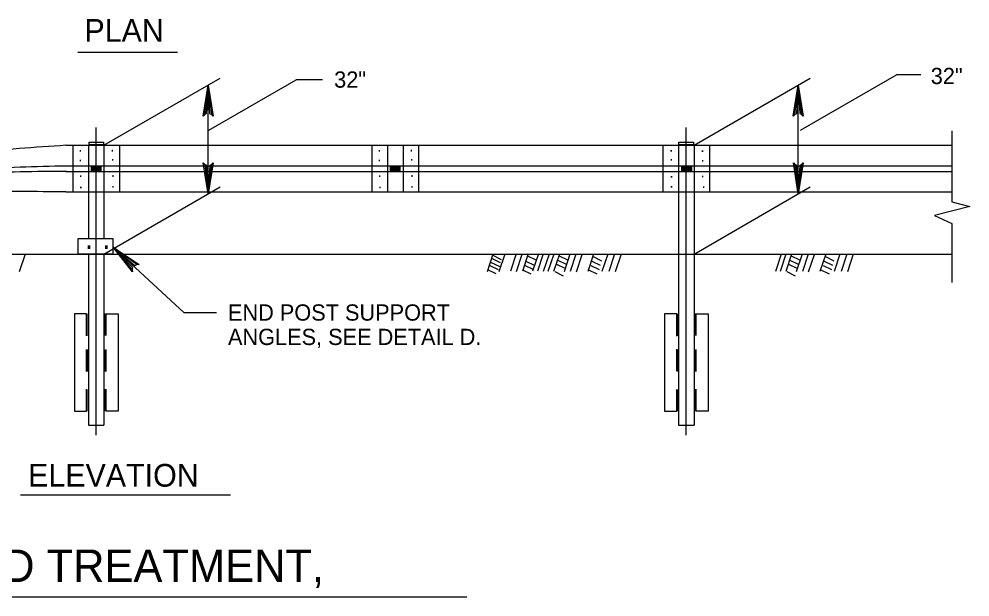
# Model space of a CAD drawing. Extents: x 637628 to 640188, y 298266 to 300751.
# Drawn here: x 638462.3 to 638638, y 298435.6 to 298542.3 of the extents above; entities that cross this region are included whole.
import ezdxf

# ---------------------------------------------------------------- set-up
doc = ezdxf.new("R2010")
doc.units = 0
doc.layers.add('2', color=7, linetype='Continuous')
doc.layers.add('3', color=7, linetype='Continuous')

msp = doc.modelspace()

# ---------------------------------------------------------------- linework, layer by layer
at = {"layer": '2'}
for p, q in [((638478.02, 298518.96), (638499.51, 298531.36)), ((638497.4, 298521.73), (638513.51, 298531.03)), ((638518.4, 298531.03), (638513.51, 298531.03)), ((638587.04, 298518.96), (638608.52, 298531.36)), ((638606.72, 298521.73), (638624.43, 298531.95)), ((638628.94, 298531.95), (638624.43, 298531.95)), ((638497.28, 298509.99), (638497.28, 298530.08)), ((638606.29, 298509.99), (638606.29, 298530.08)), ((638476.59, 298465.42), (638476.59, 298522.27)), ((638585.6, 298465.42), (638585.6, 298522.27)), ((638634.69, 298521.61), (638634.69, 298508.53)), ((638471, 298518.96), (638634.69, 298518.96)), ((638472.29, 298518.96), (638472.29, 298510.34)), ((638475.15, 298518.96), (638475.15, 298510.35)), ((638478.02, 298518.96), (638478.02, 298510.35)), ((638480.89, 298518.96), (638480.89, 298510.34)), ((638527.53, 298518.96), (638527.53, 298510.34)), ((638530.4, 298518.96), (638530.4, 298510.35)), ((638533.27, 298518.96), (638533.27, 298510.35)), ((638536.13, 298518.96), (638536.13, 298510.34)), ((638581.3, 298518.96), (638581.3, 298510.34)), ((638584.17, 298518.96), (638584.17, 298510.35)), ((638587.04, 298518.96), (638587.04, 298510.35)), ((638589.9, 298518.96), (638589.9, 298510.34)), ((638471, 298515.17), (638634.69, 298515.17)), ((638471, 298514.14), (638634.69, 298514.14)), ((638478.02, 298498.88), (638499.51, 298511.28)), ((638587.04, 298498.88), (638608.52, 298511.28)), ((638471, 298510.35), (638634.69, 298510.35)), ((638475.15, 298510.35), (638475.15, 298501.77)), ((638478.02, 298510.35), (638478.02, 298501.77)), ((638584.17, 298510.35), (638584.17, 298498.88)), ((638587.04, 298510.35), (638587.04, 298498.88)), ((638634.69, 298504.49), (638634.69, 298493.65)), ((638338.78, 298498.88), (638634.69, 298498.88)), ((638463.46, 298498.83), (638462.38, 298495.61)), ((638475.15, 298498.88), (638475.15, 298467.32)), ((638478.02, 298498.88), (638478.02, 298467.32)), ((638549.89, 298498.83), (638548.82, 298495.61)), ((638552.07, 298498.83), (638551, 298495.61)), ((638554.18, 298498.94), (638553.11, 298495.73)), ((638555.22, 298498.81), (638554.15, 298495.59)), ((638556.41, 298498.94), (638555.33, 298495.73)), ((638558.27, 298498.94), (638557.2, 298495.73)), ((638559.18, 298498.94), (638558.1, 298495.73)), ((638560.25, 298498.88), (638559.18, 298495.66)), ((638561.11, 298498.88), (638560.03, 298495.66)), ((638562.16, 298498.88), (638561.09, 298495.66)), ((638564.09, 298498.83), (638563.02, 298495.61)), ((638565.22, 298498.87), (638564.15, 298495.66)), ((638566.32, 298498.76), (638565.24, 298495.55)), ((638568.48, 298498.88), (638567.41, 298495.66)), ((638571.08, 298498.88), (638570.01, 298495.66)), ((638572.37, 298498.88), (638571.3, 298495.66)), ((638573.56, 298498.83), (638572.48, 298495.61)), ((638584.17, 298498.88), (638584.17, 298467.32)), ((638587.04, 298498.88), (638587.04, 298467.32)), ((638603.14, 298498.88), (638602.07, 298495.66)), ((638604, 298498.88), (638602.93, 298495.66)), ((638605.06, 298498.88), (638603.99, 298495.66)), ((638606.99, 298498.83), (638605.92, 298495.61)), ((638608.12, 298498.87), (638607.05, 298495.66)), ((638609.21, 298498.76), (638608.14, 298495.55)), ((638611.37, 298498.88), (638610.3, 298495.66)), ((638613.98, 298498.88), (638612.91, 298495.66)), ((638615.27, 298498.88), (638614.19, 298495.66)), ((638616.45, 298498.83), (638615.38, 298495.61)), ((638549.46, 298497.41), (638551.27, 298496.51)), ((638549.71, 298498.08), (638551.22, 298497.33)), ((638549.89, 298498.65), (638551.4, 298497.89)), ((638555.96, 298497.59), (638557.5, 298496.82)), ((638556.27, 298498.58), (638557.82, 298497.81)), ((638561.6, 298497.03), (638563.14, 298496.26)), ((638561.85, 298497.77), (638563.39, 298497)), ((638562.1, 298498.58), (638563.64, 298497.81)), ((638568.16, 298497.59), (638569.71, 298496.82)), ((638568.41, 298498.4), (638569.95, 298497.63)), ((638604.5, 298497.03), (638606.04, 298496.26)), ((638604.74, 298497.77), (638606.29, 298497)), ((638604.99, 298498.58), (638606.54, 298497.81)), ((638611.06, 298497.59), (638612.6, 298496.82)), ((638611.31, 298498.4), (638612.85, 298497.63)), ((638549.02, 298495.97), (638550.44, 298495.26)), ((638549.33, 298496.78), (638550.87, 298496.01)), ((638555.33, 298495.97), (638556.88, 298495.2)), ((638555.71, 298496.85), (638557.26, 298496.08)), ((638561.29, 298495.66), (638562.83, 298494.89)), ((638567.54, 298495.97), (638569.08, 298495.2)), ((638567.98, 298496.78), (638569.53, 298496.01)), ((638604.18, 298495.66), (638605.73, 298494.89)), ((638610.43, 298495.97), (638611.98, 298495.2)), ((638610.88, 298496.78), (638612.42, 298496.01)), ((638475.01, 298487.83), (638475.01, 298483.79)), ((638478.21, 298487.88), (638478.21, 298483.85)), ((638584.02, 298487.83), (638584.02, 298483.79)), ((638587.22, 298487.88), (638587.22, 298483.85)), ((638474.98, 298481.25), (638474.98, 298477.22)), ((638478.15, 298481.22), (638478.15, 298477.19)), ((638583.99, 298481.25), (638583.99, 298477.22)), ((638587.16, 298481.22), (638587.16, 298477.19)), ((638475.01, 298473.9), (638475.01, 298469.87)), ((638478.24, 298473.93), (638478.24, 298469.89)), ((638584.02, 298473.9), (638584.02, 298469.87)), ((638587.25, 298473.93), (638587.25, 298469.89)), ((638475.15, 298467.32), (638478.02, 298467.32)), ((638584.17, 298467.32), (638587.04, 298467.32))]:
    msp.add_line(p, q, dxfattribs=at)
for points in [[(638496.6, 298524.63), (638496.99, 298524.83), (638497.28, 298530.08), (638496.6, 298524.63), (638496.36, 298524.35), (638497.28, 298530.08), (638497.54, 298524.84), (638497.93, 298524.64), (638497.28, 298530.08), (638498.19, 298524.35), (638497.93, 298524.64)], [(638605.61, 298524.63), (638606, 298524.83), (638606.29, 298530.08), (638605.61, 298524.63), (638605.37, 298524.35), (638606.29, 298530.08), (638606.55, 298524.84), (638606.94, 298524.64), (638606.29, 298530.08), (638607.2, 298524.35), (638606.94, 298524.64)], [(638497.96, 298515.44), (638497.57, 298515.24), (638497.28, 298509.99), (638497.96, 298515.44), (638498.2, 298515.72), (638497.28, 298509.99), (638497.02, 298515.24), (638496.63, 298515.43), (638497.28, 298509.99), (638496.37, 298515.72), (638496.63, 298515.43)], [(638606.98, 298515.44), (638606.58, 298515.24), (638606.29, 298509.99), (638606.98, 298515.44), (638607.22, 298515.72), (638606.29, 298509.99), (638606.03, 298515.24), (638605.64, 298515.43), (638606.29, 298509.99), (638605.38, 298515.72), (638605.64, 298515.43)], [(638634.69, 298508.53), (638638.01, 298507.67), (638631.48, 298505.98), (638634.69, 298504.49)], [(638498.84, 298488.02), (638492.84, 298488.02), (638479.69, 298500.14)], [(638483.23, 298495.95), (638483.35, 298496.37), (638479.69, 298500.14), (638483.23, 298495.95), (638483.27, 298495.58), (638479.69, 298500.14), (638483.72, 298496.78), (638484.12, 298496.94), (638479.69, 298500.14), (638484.51, 298496.93), (638484.12, 298496.94)], [(638474.81, 298483.77), (638474.81, 298487.85), (638472.58, 298487.85), (638472.58, 298469.85), (638474.81, 298469.85), (638474.81, 298473.94)], [(638478.4, 298483.84), (638478.4, 298487.86), (638480.63, 298487.86), (638480.63, 298469.86), (638478.4, 298469.86), (638478.4, 298473.91)], [(638583.83, 298483.7), (638583.83, 298487.85), (638581.59, 298487.85), (638581.59, 298469.85), (638583.83, 298469.85), (638583.83, 298473.9)], [(638587.41, 298483.86), (638587.41, 298487.86), (638589.65, 298487.86), (638589.65, 298469.86), (638587.41, 298469.86), (638587.41, 298473.93)], [(638474.81, 298477.23), (638474.81, 298481.24)], [(638478.4, 298477.2), (638478.4, 298481.24)], [(638583.83, 298477.25), (638583.83, 298481.32)], [(638587.41, 298477.19), (638587.41, 298481.25)]]:
    msp.add_lwpolyline(points, dxfattribs=at)
for points in [[(638475.26, 298519.07), (638475.26, 298519.53), (638477.96, 298519.53), (638477.96, 298519.07)], [(638584.23, 298519.04), (638584.23, 298519.51), (638586.93, 298519.51), (638586.93, 298519.04)], [(638475.7, 298514.18), (638475.7, 298515.11), (638477.47, 298515.11), (638477.47, 298514.18)], [(638475.73, 298514.2), (638475.73, 298515.09), (638477.41, 298515.09), (638477.41, 298514.2)], [(638475.77, 298514.23), (638475.77, 298515.07), (638477.36, 298515.07), (638477.36, 298514.23)], [(638475.8, 298514.25), (638475.8, 298515.05), (638477.31, 298515.05), (638477.31, 298514.25)], [(638475.83, 298514.27), (638475.83, 298515.03), (638477.26, 298515.03), (638477.26, 298514.27)], [(638475.85, 298514.29), (638475.85, 298515.02), (638477.22, 298515.02), (638477.22, 298514.29)], [(638475.88, 298514.31), (638475.88, 298515), (638477.18, 298515), (638477.18, 298514.31)], [(638475.9, 298514.33), (638475.9, 298514.98), (638477.14, 298514.98), (638477.14, 298514.33)], [(638475.93, 298514.35), (638475.93, 298514.97), (638477.1, 298514.97), (638477.1, 298514.35)], [(638475.95, 298514.36), (638475.95, 298514.95), (638477.07, 298514.95), (638477.07, 298514.36)], [(638475.98, 298514.38), (638475.98, 298514.94), (638477.04, 298514.94), (638477.04, 298514.38)], [(638476.01, 298514.39), (638476.01, 298514.92), (638477.02, 298514.92), (638477.02, 298514.39)], [(638476.04, 298514.4), (638476.04, 298514.91), (638476.99, 298514.91), (638476.99, 298514.4)], [(638476.07, 298514.41), (638476.07, 298514.89), (638476.98, 298514.89), (638476.98, 298514.41)], [(638476.09, 298514.42), (638476.09, 298514.88), (638476.95, 298514.88), (638476.95, 298514.42)], [(638476.11, 298514.43), (638476.11, 298514.87), (638476.93, 298514.87), (638476.93, 298514.43)], [(638476.14, 298514.44), (638476.14, 298514.86), (638476.92, 298514.86), (638476.92, 298514.44)], [(638476.16, 298514.45), (638476.16, 298514.84), (638476.9, 298514.84), (638476.9, 298514.45)], [(638476.18, 298514.46), (638476.18, 298514.83), (638476.88, 298514.83), (638476.88, 298514.46)], [(638476.2, 298514.47), (638476.2, 298514.82), (638476.87, 298514.82), (638476.87, 298514.47)], [(638476.22, 298514.48), (638476.22, 298514.81), (638476.85, 298514.81), (638476.85, 298514.48)], [(638476.23, 298514.49), (638476.23, 298514.8), (638476.84, 298514.8), (638476.84, 298514.49)], [(638476.25, 298514.49), (638476.25, 298514.8), (638476.82, 298514.8), (638476.82, 298514.49)], [(638476.26, 298514.5), (638476.26, 298514.79), (638476.81, 298514.79), (638476.81, 298514.5)], [(638476.28, 298514.51), (638476.28, 298514.78), (638476.8, 298514.78), (638476.8, 298514.51)], [(638476.29, 298514.51), (638476.29, 298514.77), (638476.79, 298514.77), (638476.79, 298514.51)], [(638476.31, 298514.52), (638476.31, 298514.77), (638476.77, 298514.77), (638476.77, 298514.52)], [(638476.32, 298514.52), (638476.32, 298514.76), (638476.76, 298514.76), (638476.76, 298514.52)], [(638476.33, 298514.53), (638476.33, 298514.75), (638476.75, 298514.75), (638476.75, 298514.53)], [(638476.34, 298514.53), (638476.34, 298514.75), (638476.74, 298514.75), (638476.74, 298514.53)], [(638476.35, 298514.54), (638476.35, 298514.74), (638476.73, 298514.74), (638476.73, 298514.54)], [(638476.36, 298514.54), (638476.36, 298514.73), (638476.73, 298514.73), (638476.73, 298514.54)], [(638476.37, 298514.55), (638476.37, 298514.73), (638476.72, 298514.73), (638476.72, 298514.55)], [(638476.38, 298514.55), (638476.38, 298514.72), (638476.71, 298514.72), (638476.71, 298514.55)], [(638476.39, 298514.56), (638476.39, 298514.72), (638476.7, 298514.72), (638476.7, 298514.56)], [(638530.94, 298514.18), (638530.94, 298515.11), (638532.71, 298515.11), (638532.71, 298514.18)], [(638530.97, 298514.2), (638530.97, 298515.09), (638532.65, 298515.09), (638532.65, 298514.2)], [(638531.01, 298514.23), (638531.01, 298515.07), (638532.6, 298515.07), (638532.6, 298514.23)], [(638531.04, 298514.25), (638531.04, 298515.05), (638532.55, 298515.05), (638532.55, 298514.25)], [(638531.07, 298514.27), (638531.07, 298515.03), (638532.5, 298515.03), (638532.5, 298514.27)], [(638531.09, 298514.29), (638531.09, 298515.02), (638532.46, 298515.02), (638532.46, 298514.29)], [(638531.12, 298514.31), (638531.12, 298515), (638532.42, 298515), (638532.42, 298514.31)], [(638531.14, 298514.33), (638531.14, 298514.98), (638532.38, 298514.98), (638532.38, 298514.33)], [(638531.17, 298514.35), (638531.17, 298514.97), (638532.34, 298514.97), (638532.34, 298514.35)], [(638531.19, 298514.36), (638531.19, 298514.95), (638532.31, 298514.95), (638532.31, 298514.36)], [(638531.22, 298514.38), (638531.22, 298514.94), (638532.28, 298514.94), (638532.28, 298514.38)], [(638531.25, 298514.39), (638531.25, 298514.92), (638532.26, 298514.92), (638532.26, 298514.39)], [(638531.28, 298514.4), (638531.28, 298514.91), (638532.23, 298514.91), (638532.23, 298514.4)], [(638531.31, 298514.41), (638531.31, 298514.89), (638532.22, 298514.89), (638532.22, 298514.41)], [(638531.33, 298514.42), (638531.33, 298514.88), (638532.19, 298514.88), (638532.19, 298514.42)], [(638531.35, 298514.43), (638531.35, 298514.87), (638532.17, 298514.87), (638532.17, 298514.43)], [(638531.38, 298514.44), (638531.38, 298514.86), (638532.16, 298514.86), (638532.16, 298514.44)], [(638531.4, 298514.45), (638531.4, 298514.84), (638532.14, 298514.84), (638532.14, 298514.45)], [(638531.42, 298514.46), (638531.42, 298514.83), (638532.12, 298514.83), (638532.12, 298514.46)], [(638531.44, 298514.47), (638531.44, 298514.82), (638532.11, 298514.82), (638532.11, 298514.47)], [(638531.46, 298514.48), (638531.46, 298514.81), (638532.09, 298514.81), (638532.09, 298514.48)], [(638531.47, 298514.49), (638531.47, 298514.8), (638532.08, 298514.8), (638532.08, 298514.49)], [(638531.49, 298514.49), (638531.49, 298514.8), (638532.06, 298514.8), (638532.06, 298514.49)], [(638531.5, 298514.5), (638531.5, 298514.79), (638532.05, 298514.79), (638532.05, 298514.5)], [(638531.52, 298514.51), (638531.52, 298514.78), (638532.04, 298514.78), (638532.04, 298514.51)], [(638531.53, 298514.51), (638531.53, 298514.77), (638532.03, 298514.77), (638532.03, 298514.51)], [(638531.55, 298514.52), (638531.55, 298514.77), (638532.01, 298514.77), (638532.01, 298514.52)], [(638531.56, 298514.52), (638531.56, 298514.76), (638532, 298514.76), (638532, 298514.52)], [(638531.57, 298514.53), (638531.57, 298514.75), (638531.99, 298514.75), (638531.99, 298514.53)], [(638531.58, 298514.53), (638531.58, 298514.75), (638531.98, 298514.75), (638531.98, 298514.53)], [(638531.59, 298514.54), (638531.59, 298514.74), (638531.97, 298514.74), (638531.97, 298514.54)], [(638531.6, 298514.54), (638531.6, 298514.73), (638531.97, 298514.73), (638531.97, 298514.54)], [(638531.61, 298514.55), (638531.61, 298514.73), (638531.96, 298514.73), (638531.96, 298514.55)], [(638531.62, 298514.55), (638531.62, 298514.72), (638531.95, 298514.72), (638531.95, 298514.55)], [(638531.63, 298514.56), (638531.63, 298514.72), (638531.94, 298514.72), (638531.94, 298514.56)], [(638584.8, 298514.16), (638584.8, 298515.09), (638586.57, 298515.09), (638586.57, 298514.16)], [(638584.84, 298514.18), (638584.84, 298515.07), (638586.52, 298515.07), (638586.52, 298514.18)], [(638584.87, 298514.21), (638584.87, 298515.05), (638586.46, 298515.05), (638586.46, 298514.21)], [(638584.9, 298514.23), (638584.9, 298515.03), (638586.41, 298515.03), (638586.41, 298514.23)], [(638584.93, 298514.25), (638584.93, 298515.02), (638586.37, 298515.02), (638586.37, 298514.25)], [(638584.95, 298514.28), (638584.95, 298515), (638586.32, 298515), (638586.32, 298514.28)], [(638584.98, 298514.3), (638584.98, 298514.98), (638586.28, 298514.98), (638586.28, 298514.3)], [(638585, 298514.31), (638585, 298514.97), (638586.24, 298514.97), (638586.24, 298514.31)], [(638585.03, 298514.33), (638585.03, 298514.95), (638586.2, 298514.95), (638586.2, 298514.33)], [(638585.05, 298514.35), (638585.05, 298514.94), (638586.17, 298514.94), (638586.17, 298514.35)], [(638585.08, 298514.36), (638585.08, 298514.92), (638586.14, 298514.92), (638586.14, 298514.36)], [(638585.11, 298514.37), (638585.11, 298514.9), (638586.12, 298514.9), (638586.12, 298514.37)], [(638585.14, 298514.38), (638585.14, 298514.89), (638586.1, 298514.89), (638586.1, 298514.38)], [(638585.17, 298514.4), (638585.17, 298514.88), (638586.08, 298514.88), (638586.08, 298514.4)], [(638585.19, 298514.41), (638585.19, 298514.86), (638586.05, 298514.86), (638586.05, 298514.41)], [(638585.21, 298514.42), (638585.21, 298514.85), (638586.04, 298514.85), (638586.04, 298514.42)], [(638585.24, 298514.43), (638585.24, 298514.84), (638586.02, 298514.84), (638586.02, 298514.43)], [(638585.26, 298514.44), (638585.26, 298514.83), (638586, 298514.83), (638586, 298514.44)], [(638585.28, 298514.44), (638585.28, 298514.82), (638585.98, 298514.82), (638585.98, 298514.44)], [(638585.3, 298514.45), (638585.3, 298514.81), (638585.97, 298514.81), (638585.97, 298514.45)], [(638585.32, 298514.46), (638585.32, 298514.8), (638585.95, 298514.8), (638585.95, 298514.46)], [(638585.33, 298514.47), (638585.33, 298514.79), (638585.94, 298514.79), (638585.94, 298514.47)], [(638585.35, 298514.48), (638585.35, 298514.78), (638585.92, 298514.78), (638585.92, 298514.48)], [(638585.36, 298514.48), (638585.36, 298514.77), (638585.91, 298514.77), (638585.91, 298514.48)], [(638585.38, 298514.49), (638585.38, 298514.76), (638585.9, 298514.76), (638585.9, 298514.49)], [(638585.39, 298514.5), (638585.39, 298514.76), (638585.89, 298514.76), (638585.89, 298514.5)], [(638585.41, 298514.5), (638585.41, 298514.75), (638585.87, 298514.75), (638585.87, 298514.5)], [(638585.42, 298514.51), (638585.42, 298514.74), (638585.86, 298514.74), (638585.86, 298514.51)], [(638585.43, 298514.51), (638585.43, 298514.74), (638585.85, 298514.74), (638585.85, 298514.51)], [(638585.44, 298514.52), (638585.44, 298514.73), (638585.84, 298514.73), (638585.84, 298514.52)], [(638585.45, 298514.52), (638585.45, 298514.72), (638585.83, 298514.72), (638585.83, 298514.52)], [(638585.46, 298514.53), (638585.46, 298514.72), (638585.83, 298514.72), (638585.83, 298514.53)], [(638585.47, 298514.53), (638585.47, 298514.71), (638585.82, 298514.71), (638585.82, 298514.53)], [(638585.48, 298514.54), (638585.48, 298514.71), (638585.81, 298514.71), (638585.81, 298514.54)], [(638585.49, 298514.54), (638585.49, 298514.7), (638585.8, 298514.7), (638585.8, 298514.54)], [(638479.63, 298501.77), (638479.63, 298498.84), (638473.23, 298498.84), (638473.23, 298501.77)]]:
    msp.add_lwpolyline(points, close=True, dxfattribs=at)
for points in [[(638471, 298518.96), (638453.71, 298517.53), (638442.95, 298516.06), (638429.84, 298513.59), (638422.02, 298511.59)], [(638471.09, 298515.13), (638453.96, 298514.5), (638443.34, 298513.54), (638430.34, 298511.69), (638421.81, 298509.92), (638414.88, 298507.17), (638408.57, 298503.69), (638404.49, 298500.62)], [(638471.09, 298514.14), (638454, 298513.77), (638443.42, 298512.98), (638430.45, 298511.34), (638422.01, 298509.73), (638415.18, 298507.14), (638408.94, 298503.83), (638404.93, 298500.9)], [(638471, 298510.35), (638454.11, 298510.29), (638443.71, 298509.69), (638430.93, 298508.31), (638423.1, 298506.95)]]:
    msp.add_spline(points, degree=3, dxfattribs=at)
at = {"layer": '3'}
for p, q in [((638473.19, 298536.16), (638491.62, 298536.16)), ((638462.57, 298454.44), (638501.38, 298454.44)), ((638406.98, 298435.58), (638545.08, 298435.58))]:
    msp.add_line(p, q, dxfattribs=at)

# ---------------------------------------------------------------- texts
for s, height, p in [('PLAN', 4.2, (638474.41, 298538.06)), ('32"', 3, (638520.55, 298529.59)), ('32"', 3, (638630.77, 298530.25)), ('.', 2.07, (638473.26, 298517.77)), ('.', 2.07, (638479.19, 298517.8)), ('.', 2.07, (638528.5, 298517.77)), ('.', 2.07, (638534.44, 298517.8)), ('.', 2.07, (638582.43, 298517.78)), ('.', 2.07, (638588.22, 298517.73)), ('.', 2.07, (638473.27, 298516)), ('.', 2.07, (638479.23, 298516.1)), ('.', 2.07, (638528.52, 298516)), ('.', 2.07, (638534.47, 298516.1)), ('.', 2.07, (638582.44, 298516.1)), ('.', 2.07, (638588.23, 298515.95)), ('.', 2.07, (638473.34, 298513.1)), ('.', 2.07, (638479.31, 298513.13)), ('.', 2.07, (638528.58, 298513.1)), ('.', 2.07, (638534.55, 298513.13)), ('.', 2.07, (638582.49, 298512.98)), ('.', 2.07, (638588.23, 298513.03)), ('.', 2.07, (638473.37, 298511)), ('.', 2.07, (638479.31, 298511.12)), ('.', 2.07, (638528.62, 298511)), ('.', 2.07, (638534.55, 298511.12)), ('.', 2.07, (638582.49, 298511.14)), ('.', 2.07, (638588.43, 298511.05)), ('.', 4.13, (638474.49, 298499.82)), ('.', 4.13, (638477.68, 298499.82)), ('END POST SUPPORT', 2.9999, (638500.93, 298486.59)), ('ANGLES, SEE DETAIL D.', 2.9999, (638500.93, 298482.09)), ('ELEVATION', 4.2, (638464, 298455.94)), ('TYPE 2-W END TREATMENT,', 6, (638408.13, 298438.34))]:
    msp.add_text(s, height=height, dxfattribs=at).set_placement(p)

doc.saveas('drawing.dxf')
